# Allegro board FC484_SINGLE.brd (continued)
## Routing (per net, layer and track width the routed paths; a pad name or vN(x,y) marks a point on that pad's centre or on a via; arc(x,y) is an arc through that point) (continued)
IO51: length 6.3
  TOP w0.254: U1.K5 v1(47.81,61.23)
  L4_SIG2 w0.102: v1(47.81,61.23) 47.32,61.73 42.42,61.73
IO52: length 5.5
  TOP w0.254: U1.M4 v1(46.81,58.23)
  L3_SIG1 w0.102: v1(46.81,58.23) 46.32,58.73 44.45,58.73 43.95,58.23 42.45,58.23
IO53: length 4.2
  TOP w0.254: U1.L3 v1(45.81,60.23)
  L3_SIG1 w0.102: v1(45.81,60.23) 45.55,60.23 45.13,59.81 44.23,59.81 44.11,59.94 44.1,59.94 43.81,60.23 42.63,60.23
IO54: length 6.6
  TOP w0.254: U1.M5 v1(47.81,58.23)
  L3_SIG1 w0.102: v1(47.81,58.23) 46.96,59.09 43.96,59.09 43.81,59.23 43.81,59.23 43.63,59.41 42.43,59.41
IO55: length 6.5
  TOP w0.254: U1.L5 v1(47.81,60.23)
  L3_SIG1 w0.102: 42.56,59.87 43.67,59.87 43.95,59.59 43.96,59.59 44.09,59.46 47.04,59.46 v1(47.81,60.23)
IO56: length 2.4
  TOP w0.127: U1.L1 41.92,59.73
IO57: length 2.4
  TOP w0.127: U1.K1 41.92,60.73
IO58: length 3.9
  TOP w0.127: U1.J2 44.82,62.23 41.67,62.23
IO59: length 4
  TOP w0.254: U1.J3 v1(45.81,62.23)
  L3_SIG1 w0.102: v1(45.81,62.23) 44.32,62.23 44.25,62.17 42.58,62.17
IO60: length 3.9
  TOP w0.127: 41.67,60.23 44.82,60.23 U1.L2
IO61: length 4.3
  TOP w0.254: U1.K3 v1(45.81,61.23)
  L3_SIG1 w0.102: v1(45.81,61.23) 45.52,61.23 44.97,60.68 44.37,60.68 44.11,60.94 42.57,60.94
IO62: length 2.4
  TOP w0.127: U1.J1 41.92,61.73
IO63: length 2.4
  TOP w0.127: U1.H1 41.92,62.73
IO64: length 2.5
  TOP w0.127: U1.F1 41.77,64.73
IO65: length 3.9
  TOP w0.127: U1.F2 44.82,65.23 41.67,65.23
IO66: length 3.9
  TOP w0.127: U1.H2 44.82,63.23 41.67,63.23
IO67: length 3.9
  TOP w0.127: 41.67,64.23 44.82,64.23 U1.G2
IO68: length 7.3
  TOP w0.254: U1.F12 v1(55.81,65.23)
  L3_SIG1 w0.102: v1(55.81,65.23) 55.23,65.82 55.23,71.55
IO69: length 8
  TOP w0.254: U1.F13 v1(56.81,65.23)
  L4_SIG2 w0.102: v1(56.81,65.23) 56.81,65.26 56.34,65.73 55.61,65.73 55.26,66.09 55.26,71.49
IO70: length 7.4
  TOP w0.254: U1.F11 v1(53.81,65.23)
  L3_SIG1 w0.102: v1(53.81,65.23) 54.79,66.2 54.79,71.55
IO71: length 6.2
  TOP w0.254: U1.E11 v1(53.81,66.23)
  L3_SIG1 w0.102: 54.32,71.55 54.32,66.74 v1(53.81,66.23)
IO72: length 7.2
  TOP w0.254: U1.K6 v1(48.81,61.23)
  L4_SIG2 w0.102: 42.48,60.73 48.31,60.73 v1(48.81,61.23)
IO73: length 7.1
  TOP w0.254: U1.J6 v1(48.81,62.23)
  L4_SIG2 w0.102: v1(48.81,62.23) 48.32,62.73 42.63,62.73
IO74: length 9
  TOP w0.254: U1.J7 v1(49.81,62.23)
  L5_SIG3 w0.102: v1(49.81,62.23) 49.32,62.73 41.71,62.73
IO75: length 9.2
  TOP w0.254: U1.H7 v1(49.81,63.23)
  L5_SIG3 w0.102: 41.82,64.34 43.87,64.34 44.48,63.73 49.11,63.73 49.61,63.23 v1(49.81,63.23)
IO76: length 6.3
  TOP w0.254: U1.E13 v1(56.81,66.23)
  L4_SIG2 w0.102: 56.31,71.64 56.31,66.73 v1(56.81,66.23)
IO77: length 5.5
  TOP w0.254: U1.D13 v1(56.81,67.23)
  L3_SIG1 w0.102: 56.82,71.55 56.82,69.77 57.36,69.23 57.36,67.78 v1(56.81,67.23)
IO78: length 9.7
  TOP w0.254: U1.K8 v1(50.81,61.23)
  L5_SIG3 w0.102: v1(50.81,61.23) 50.32,61.73 42,61.73
IO79: length 11.5
  TOP w0.254: U1.J8 v1(50.81,62.23)
  L5_SIG3 w0.102: 41.84,65.1 43.72,65.1 44.09,64.73 49.02,64.73 49.31,64.44 49.31,64.03 49.61,63.73 50.02,63.73 50.31,63.44 50.31,62.73 v1(50.81,62.23)
IO80: length 4.9
  TOP w0.254: U1.J4 v1(46.81,62.23)
  L3_SIG1 w0.102: v1(46.81,62.23) 46.32,61.73 42.88,61.73
IO81: length 5.2
  TOP w0.254: U1.H4 v1(46.81,63.23)
  L3_SIG1 w0.102: v1(46.81,63.23) 46.32,62.73 44.32,62.73 44.11,62.52 42.63,62.52
IO82: length 6.7
  TOP w0.254: U1.H5 v1(47.81,63.23)
  L4_SIG2 w0.102: 42.28,64.24 43.93,64.24 44.45,63.73 47.32,63.73 v1(47.81,63.23)
IO83: length 8.3
  TOP w0.254: U1.H6 v1(48.81,63.23)
  L4_SIG2 w0.102: 42.28,64.73 48.02,64.73 48.31,64.44 48.31,63.73 v1(48.81,63.23)
IO84: length 11
  TOP w0.254: U1.K9 v1(51.81,61.23)
  L5_SIG3 w0.102: 42.67,59.37 50.65,59.37 51.31,60.03 51.31,60.73 v1(51.81,61.23)
IO85: length 10
  TOP w0.254: U1.J9 v1(51.81,62.23)
  L5_SIG3 w0.102: v1(51.81,62.23) 51.31,62.73 51.31,71.28
IO86: length 2.5
  TOP w0.127: U1.D1 41.77,66.73
IO87: length 2.5
  TOP w0.127: U1.E1 41.77,65.73
IO88: length 3.9
  TOP w0.127: 41.67,68.23 44.82,68.23 U1.C2
IO89: length 3.9
  TOP w0.127: U1.D2 44.82,67.23 41.67,67.23
IO90: length 2.5
  TOP w0.127: U1.B1 41.77,68.73
IO91: length 2.5
  TOP w0.127: U1.C1 41.77,67.73
IO92: length 2.5
  TOP w0.127: U1.A3 46.31,72.26
IO93: length 2.5
  TOP w0.127: U1.A2 45.31,72.28
IO94: length 4.3
  TOP w0.254: U1.D3 v1(45.81,67.23)
  L3_SIG1 w0.102: v1(45.81,67.23) 42.21,67.23
IO95: length 4.2
  TOP w0.254: U1.E3 v1(45.81,66.23)
  L3_SIG1 w0.102: 42.57,65.73 45.02,65.73 45.52,66.23 v1(45.81,66.23)
IO96: length 3.5
  TOP w0.127: U1.B3 45.82,69.23 45.82,72.04
IO97: length 3.8
  TOP w0.127: 44.82,72.29 44.82,69.23 U1.B2
IO98: length 6.6
  TOP w0.254: U1.E14 v1(57.81,66.23)
  L4_SIG2 w0.102: 57.81,71.75 57.81,70.23 57.32,69.74 57.32,66.73 v1(57.81,66.23)
IO99: length 5
  TOP w0.254: U1.D14 v1(57.81,67.23)
  L3_SIG1 w0.102: v1(57.81,67.23) 57.81,71.55
IO100: length 7.2
  TOP w0.254: U1.E5 v1(47.81,66.23)
  L3_SIG1 w0.102: 42.25,67.73 46.02,67.73 46.31,67.44 46.31,66.97 46.54,66.73 47.1,66.73 47.6,66.23 v1(47.81,66.23)
IO101: length 6.3
  TOP w0.254: U1.F5 v1(47.81,65.23)
  L3_SIG1 w0.102: 42.63,65.28 45.08,65.28 45.54,65.73 47.32,65.73 v1(47.81,65.23)
IO102: length 4.1
  TOP w0.254: U1.C4 v1(46.81,68.23)
  L3_SIG1 w0.102: v1(46.81,68.23) 46.81,68.48 46.42,68.87 46.42,71.41
IO103: length 5.1
  TOP w0.254: U1.D4 v1(46.81,67.23)
  L3_SIG1 w0.102: v1(46.81,67.23) 46.81,67.53 46.32,68.03 46.32,68.19 46.31,68.19 46.31,68.48 46.06,68.72 46.06,71.32
IO104: length 5.4
  TOP w0.254: U1.E4 v1(46.81,66.23)
  L3_SIG1 w0.102: 42.36,66.73 46.02,66.73 46.52,66.23 v1(46.81,66.23)
IO105: length 4
  TOP w0.254: U1.F3 v1(45.81,65.23)
  L3_SIG1 w0.102: 42.63,64.89 45.21,64.89 45.55,65.23 v1(45.81,65.23)
IO106: length 2.5
  TOP w0.127: U1.A5 48.31,72.19
IO107: length 3.7
  TOP w0.127: 46.82,72.21 46.82,69.23 U1.B4
IO108: length 5.5
  TOP w0.254: U1.D6 v1(48.81,67.23)
  L3_SIG1 w0.102: v1(48.81,67.23) 48.31,67.73 48.31,68.51 47.81,69.02 47.81,69.73 48.17,70.09 48.17,71.42
IO109: length 6.7
  TOP w0.254: U1.E6 v1(48.81,66.23)
  L3_SIG1 w0.102: v1(48.81,66.23) 48.32,66.73 47.61,66.73 47.32,67.03 47.32,68.49 46.78,69.03 46.78,70.96
IO110: length 3.6
  TOP w0.127: 47.82,72.16 47.82,69.23 U1.B5
IO111: length 4.2
  TOP w0.254: U1.C5 v1(47.81,68.23)
  L3_SIG1 w0.102: v1(47.81,68.23) 47.81,68.5 47.4,68.92 47.4,69.82 47.81,70.23 47.81,71.41
IO112: length 4.1
  TOP w0.254: U1.C15 v1(58.81,68.23)
  L3_SIG1 w0.102: v1(58.81,68.23) 58.52,68.52 58.52,71.55
IO113: length 4.8
  TOP w0.127: U1.C14 57.81,68.23 57.81,72.36
IO114: length 3.9
  TOP w0.127: U1.B17 60.82,69.24 60.82,72.45
IO115: length 2.7
  TOP w0.127: U1.A17 60.31,72.44
IO116: length 3.9
  TOP w0.127: 58.81,72.44 58.81,69.23 U1.B15
IO117: length 3.9
  TOP w0.127: 56.81,72.44 56.81,69.24 U1.B14
IO118: length 4.1
  TOP w0.254: U1.C17 v1(60.81,68.23)
  L3_SIG1 w0.102: v1(60.81,68.23) 60.81,71.64
IO119: length 4.2
  TOP w0.254: U1.C16 v1(59.81,68.23)
  L3_SIG1 w0.102: v1(59.81,68.23) 59.81,68.49 59.3,69 59.3,71.55
IO120: length 2.7
  TOP w0.127: U1.A16 59.31,72.44
IO121: length 2.7
  TOP w0.127: U1.A15 58.31,72.44
IO122: length 4.9
  TOP w0.254: U1.D8 v1(50.81,67.23)
  L3_SIG1 w0.102: 50.32,71.25 50.32,67.73 v1(50.81,67.23)
IO123: length 6.3
  TOP w0.254: U1.E8 v1(50.81,66.23)
  L4_SIG2 w0.102: 51.31,71.66 51.31,66.73 v1(50.81,66.23)
IO124: length 12.5
  TOP w0.254: U1.H13 v1(56.81,63.23)
  L4_SIG2 w0.102: 67.58,61.73 57.61,61.73 57.32,62.03 57.32,62.73 v1(56.81,63.23)
IO125: length 8.1
  TOP w0.254: U1.G14 v1(57.81,64.23)
  L4_SIG2 w0.102: 58.31,71.39 58.31,64.73 v1(57.81,64.23)
IO126: length 9.3
  TOP w0.254: U1.G15 v1(58.81,64.23)
  L4_SIG2 w0.102: v1(58.81,64.23) 59.32,64.73 67.16,64.73
IO127: length 9.5
  TOP w0.254: U1.H15 v1(58.81,63.23)
  L4_SIG2 w0.102: 67.41,62.73 59.31,62.73 v1(58.81,63.23)
IO128: length 5.2
  TOP w0.254: U1.D17 v1(60.81,67.23)
  L3_SIG1 w0.102: v1(60.81,67.23) 61.32,67.73 61.32,71.56
IO129: length 5.2
  TOP w0.254: U1.D16 v1(59.81,67.23)
  L3_SIG1 w0.102: v1(59.81,67.23) 60.31,67.73 60.31,71.51
IO130: length 6.4
  TOP w0.254: U1.E16 v1(59.81,66.23)
  L3_SIG1 w0.102: 58.88,71.55 58.88,68.92 59.32,68.48 59.32,66.73 v1(59.81,66.23)
IO131: length 6.3
  TOP w0.254: U1.E15 v1(58.81,66.23)
  L3_SIG1 w0.102: v1(58.81,66.23) 58.32,66.73 58.32,68.22 58.17,68.37 58.17,71.55
IO132: length 7.7
  TOP w0.254: U1.F17 v1(60.81,65.23)
  L4_SIG2 w0.102: v1(60.81,65.23) 61.31,65.73 61.31,72
IO133: length 7.4
  TOP w0.254: U1.G17 v1(60.81,64.23)
  L4_SIG2 w0.102: 67.29,63.73 61.32,63.73 v1(60.81,64.23)
IO134: length 7.6
  TOP w0.254: U1.F16 v1(59.81,65.23)
  L4_SIG2 w0.102: 60.31,71.94 60.31,65.73 v1(59.81,65.23)
IO135: length 7.4
  TOP w0.254: U1.F15 v1(58.81,65.23)
  L4_SIG2 w0.102: v1(58.81,65.23) 59.31,65.73 59.31,71.74
IO136: length 2.5
  TOP w0.127: U1.A7 50.31,72.19
IO137: length 2.5
  TOP w0.127: U1.A6 49.31,72.19
IO138: length 5.1
  TOP w0.254: U1.D9 v1(51.81,67.23)
  L3_SIG1 w0.102: v1(51.81,67.23) 51.31,67.73 51.31,68.48 51.06,68.72 51.06,71.32
IO139: length 6.8
  TOP w0.254: U1.E9 v1(51.81,66.23)
  L4_SIG2 w0.102: 51.76,71.93 51.76,70.29 52.31,69.74 52.31,66.73 v1(51.81,66.23)
IO140: length 2.5
  TOP w0.127: U1.A8 51.31,72.19
IO141: length 3.7
  TOP w0.127: U1.B8 50.82,69.23 50.82,72.22
IO142: length 3.9
  TOP w0.127: 55.82,72.38 55.82,69.23 U1.B13
IO143: length 4.1
  TOP w0.127: 54.82,72.59 54.82,69.23 U1.B12
IO144: length 4.2
  TOP w0.254: U1.C10 v1(52.81,68.23)
  L3_SIG1 w0.102: v1(52.81,68.23) 52.81,68.5 52.4,68.92 52.4,69.82 52.81,70.23 52.81,71.41
IO145: length 4.1
  TOP w0.254: U1.C9 v1(51.81,68.23)
  L3_SIG1 w0.102: 51.42,71.41 51.42,68.87 51.81,68.48 v1(51.81,68.23)
IO146: length 3.7
  TOP w0.127: 52.81,72.22 52.81,69.23 U1.B10
IO147: length 3.7
  TOP w0.127: U1.B9 51.82,69.23 51.82,72.27
IO148: length 4
  TOP w0.254: U1.C12 v1(55.81,68.23)
  L3_SIG1 w0.102: v1(55.81,68.23) 55.81,71.55
IO149: length 4.3
  TOP w0.254: U1.C11 v1(53.81,68.23)
  L3_SIG1 w0.102: v1(53.81,68.23) 53.81,68.53 53.26,69.08 53.26,69.68 53.52,69.94 53.52,71.48
IO150: length 7.3
  TOP w0.254: U1.T11 v1(53.81,54.23)
  L4_SIG2 w0.102: v1(53.81,54.23) 54.21,54.23 54.81,53.64 54.81,48.33
IO151: length 13.6
  TOP w0.254: U1.R12 v1(55.81,55.23)
  L4_SIG2 w0.102: 67.02,57.73 57.61,57.73 57.31,57.44 57.31,57.03 57.02,56.73 56.61,56.73 56.31,56.44 56.31,55.73 55.82,55.23 v1(55.81,55.23)
IO152: length 6
  TOP w0.254: U1.U14 v1(57.81,53.23)
  L4_SIG2 w0.102: v1(57.81,53.23) 58.31,52.73 58.31,48.14
IO153: length 6.1
  TOP w0.254: U1.V14 v1(57.81,52.23)
  L3_SIG1 w0.102: v1(57.81,52.23) 57.32,51.73 57.32,47.03
IO154: length 4.3
  TOP w0.254: U1.Y9 v1(51.81,50.23)
  L3_SIG1 w0.102: v1(51.81,50.23) 51.81,49.94 52.37,49.39 52.37,49.01 52.1,48.75 52.1,46.99
IO155: length 5.5
  TOP w0.254: U1.W9 v1(51.81,51.23)
  L3_SIG1 w0.102: 52.46,47.05 52.46,48.59 52.82,48.95 52.82,49.45 52.32,49.96 52.32,50.73 v1(51.81,51.23)
IO156: length 4.5
  TOP w0.254: U1.V10 v1(52.81,52.23)
  L4_SIG2 w0.102: 52.32,48.62 52.32,51.73 v1(52.81,52.23)
IO157: length 5.8
  TOP w0.254: U1.V9 v1(51.81,52.23)
  L3_SIG1 w0.102: v1(51.81,52.23) 51.32,51.73 51.32,47.32
IO158: length 8.4
  TOP w0.254: U1.R10 v1(52.81,55.23)
  L5_SIG3 w0.102: 53.31,47.79 53.31,54.73 v1(52.81,55.23)
IO159: length 8.4
  TOP w0.254: U1.R9 v1(51.81,55.23)
  L5_SIG3 w0.102: 52.31,47.78 52.31,54.73 v1(51.81,55.23)
IO160: length 7
  TOP w0.254: U1.U10 v1(52.81,53.23)
  L4_SIG2 w0.102: v1(52.81,53.23) 53.31,52.73 53.31,48.66 53.01,48.35 53.01,47.32
IO161: length 8.8
  TOP w0.254: U1.T10 v1(52.81,54.23)
  L4_SIG2 w0.102: v1(52.81,54.23) 53.31,53.73 54.02,53.73 54.37,53.39 54.37,48.78 53.67,48.08 53.67,47.47
IO162: length 5.7
  TOP w0.254: U1.U9 v1(51.81,53.23)
  L4_SIG2 w0.102: v1(51.81,53.23) 51.32,52.73 51.32,48.49
IO163: length 5.3
  TOP w0.254: U1.U8 v1(50.81,53.23)
  L4_SIG2 w0.102: v1(50.81,53.23) 50.81,53.03 50.32,52.53 50.32,48.8
IO164: length 7.9
  TOP w0.254: U1.T8 v1(50.81,54.23)
  L4_SIG2 w0.102: v1(50.81,54.23) 50.31,53.73 50.31,53.03 50.02,52.73 49.61,52.73 49.31,52.43 49.31,52.03 49.02,51.73 48.61,51.73 48.32,51.44 48.32,48.54
IO165: length 8.3
  TOP w0.254: U1.T7 v1(49.81,54.23)
  L4_SIG2 w0.102: v1(49.81,54.23) 49.31,53.73 44.32,53.73 43.81,53.22 42.62,53.22
IO166: length 3.8
  TOP w0.254: U1.Y8 v1(50.81,50.23)
  L3_SIG1 w0.102: v1(50.81,50.23) 50.81,47.15
IO167: length 3.9
  TOP w0.127: U1.AA8 50.82,49.23 50.82,46.09
IO168: length 2.7
  TOP w0.127: U1.AB7 50.31,45.99
IO169: length 3.9
  TOP w0.127: 49.82,46.09 49.82,49.23 U1.AA7
IO170: length 4.9
  TOP w0.254: U1.W8 v1(50.81,51.23)
  L3_SIG1 w0.102: 50.32,47.27 50.32,50.73 v1(50.81,51.23)
IO171: length 5
  TOP w0.254: U1.W7 v1(49.81,51.23)
  L3_SIG1 w0.102: v1(49.81,51.23) 49.32,50.73 49.32,48.73 49.82,48.22 49.82,47.38
IO172: length 2.9
  TOP w0.127: U1.AB5 48.31,45.86
IO173: length 3.9
  TOP w0.127: U1.AA5 47.82,49.23 47.82,46.09
IO174: length 3.9
  TOP w0.127: U1.AA6 48.82,49.23 48.82,46.09
IO175: length 3.6
  TOP w0.254: U1.Y6 v1(48.81,50.23)
  L3_SIG1 w0.102: v1(48.81,50.23) 48.81,47.33
IO176: length 4.3
  TOP w0.254: U1.V7 v1(49.81,52.23)
  L4_SIG2 w0.102: v1(49.81,52.23) 49.81,52.03 49.32,51.53 49.32,48.82
IO177: length 8.2
  TOP w0.254: U1.U7 v1(49.81,53.23)
  L4_SIG2 w0.102: v1(49.81,53.23) 49.6,53.23 49.1,52.73 42.58,52.73
IO178: length 2.9
  TOP w0.127: U1.AB4 47.31,45.86
IO179: length 2.9
  TOP w0.127: U1.AB3 46.31,45.86
IO180: length 4.9
  TOP w0.254: U1.W6 v1(48.81,51.23)
  L3_SIG1 w0.102: 48.32,47.27 48.32,50.73 v1(48.81,51.23)
IO181: length 6.5
  TOP w0.254: U1.V6 v1(48.81,52.23)
  L4_SIG2 w0.102: 43.2,51.73 48.1,51.73 48.61,52.23 v1(48.81,52.23)
IO182: length 2.9
  TOP w0.127: U1.AB2 45.31,45.86
IO183: length 3.9
  TOP w0.127: 44.82,46.09 44.82,49.23 U1.AA2
IO184: length 3.9
  TOP w0.254: U1.Y5 v1(47.81,50.23)
  L3_SIG1 w0.102: v1(47.81,50.23) 47.81,48.12 47.82,48.12 47.82,47.05
IO185: length 4.1
  TOP w0.254: U1.Y4 v1(46.81,50.23)
  L3_SIG1 w0.102: 46.24,47.04 46.24,49.36 46.81,49.94 v1(46.81,50.23)
IO186: length 3.9
  TOP w0.127: U1.AA3 45.82,49.23 45.82,46.09
IO187: length 4.1
  TOP w0.254: U1.Y3 v1(45.81,50.23)
  L3_SIG1 w0.102: v1(45.81,50.23) 45.32,49.73 42.67,49.73
IO188: length 5.4
  TOP w0.254: U1.W4 v1(46.81,51.23)
  L3_SIG1 w0.102: v1(46.81,51.23) 46.81,50.94 46.31,50.43 46.31,50.02 45.85,49.56 45.85,46.95
IO189: length 5.9
  TOP w0.254: U1.V5 v1(47.81,52.23)
  L3_SIG1 w0.102: v1(47.81,52.23) 47.81,52.03 47.32,51.53 47.32,47.21
IO190: length 2.2
  TOP w0.127: U1.AA1 42.07,49.73
IO191: length 2.2
  TOP w0.127: U1.Y1 42.07,50.73
IO192: length 3.8
  TOP w0.254: U1.W3 v1(45.81,51.23)
  L3_SIG1 w0.102: v1(45.81,51.23) 42.76,51.23
IO193: length 5.1
  TOP w0.254: U1.V4 v1(46.81,52.23)
  L3_SIG1 w0.102: 42.67,51.73 46.11,51.73 46.61,52.23 v1(46.81,52.23)
IO194: length 2.2
  TOP w0.127: U1.W1 42.07,51.73
IO195: length 2.2
  TOP w0.127: U1.V1 42.07,52.73
IO196: length 3.9
  TOP w0.127: U1.W2 44.82,51.23 41.67,51.23
IO197: length 3.9
  TOP w0.127: U1.V2 44.82,52.23 41.67,52.23
IO198: length 3.9
  TOP w0.127: U1.U2 44.82,53.23 41.67,53.23
IO199: length 4.1
  TOP w0.254: U1.U3 v1(45.81,53.23)
  L3_SIG1 w0.102: v1(45.81,53.23) 45.57,53.23 45.17,52.84 42.63,52.84
IO200: length 5.1
  TOP w0.254: U1.U4 v1(46.81,53.23)
  L3_SIG1 w0.102: v1(46.81,53.23) 46.31,52.73 45.57,52.73 45.32,52.48 42.73,52.48
IO201: length 7.4
  TOP w0.254: U1.U5 v1(47.81,53.23)
  L3_SIG1 w0.102: v1(47.81,53.23) 47.32,52.73 47.32,52.03 47.02,51.73 46.61,51.73 46.31,51.43 46.31,51.03 46.02,50.73 42.77,50.73
IO202: length 7.4
  TOP w0.254: U1.U17 v1(60.81,53.23)
  L4_SIG2 w0.102: v1(60.81,53.23) 61.32,52.73 67.25,52.73
IO203: length 10
  TOP w0.254: U1.T17 v1(60.81,54.23)
  L3_SIG1 w0.102: 65.84,59.2 64.18,59.2 63.74,58.77 61.65,58.77 61.31,58.43 61.31,54.73 v1(60.81,54.23)
IO204: length 5.3
  TOP w0.254: U1.W16 v1(59.81,51.23)
  L3_SIG1 w0.102: v1(59.81,51.23) 60.31,50.73 60.31,49.99 60.52,49.78 60.52,46.92
IO205: length 4.7
  TOP w0.254: U1.V16 v1(59.81,52.23)
  L4_SIG2 w0.102: v1(59.81,52.23) 59.82,52.23 60.32,51.73 60.32,48.47
IO206: length 7.5
  TOP w0.254: U1.V17 v1(60.81,52.23)
  L4_SIG2 w0.102: v1(60.81,52.23) 61.32,51.73 67.39,51.73
IO207: length 5.2
  TOP w0.254: U1.W17 v1(60.81,51.23)
  L3_SIG1 w0.102: 61.31,46.95 61.31,50.73 v1(60.81,51.23)
IO208: length 3.9
  TOP w0.127: 60.81,46.09 60.81,49.23 U1.AA17
IO209: length 2.9
  TOP w0.127: U1.AB17 60.31,45.88
IO210: length 4.2
  TOP w0.254: U1.Y16 v1(59.81,50.23)
  L3_SIG1 w0.102: v1(59.81,50.23) 59.81,49.99 60.17,49.63 60.17,46.87
IO211: length 3.9
  TOP w0.127: 59.81,46.09 59.81,49.23 U1.AA16
IO212: length 9.9
  TOP w0.254: U1.R16 v1(59.81,55.23)
  L3_SIG1 w0.102: v1(59.81,55.23) 60.32,55.73 60.32,58.51 60.95,59.14 63.61,59.14 64.1,59.63 65.6,59.63
IO213: length 8.3
  TOP w0.254: U1.T16 v1(59.81,54.23)
  L4_SIG2 w0.102: v1(59.81,54.23) 60.31,53.73 67.2,53.73
IO214: length 3.9
  TOP w0.127: U1.AA15 58.81,49.23 58.81,46.09
IO215: length 4.2
  TOP w0.254: U1.Y15 v1(58.81,50.23)
  L3_SIG1 w0.102: v1(58.81,50.23) 58.81,49.97 59.23,49.55 59.23,48.65 58.82,48.23 58.82,47.05
IO216: length 4.3
  TOP w0.254: U1.Y14 v1(57.81,50.23)
  L3_SIG1 w0.102: 58.1,46.99 58.1,48.53 58.37,48.79 58.37,49.4 57.81,49.96 v1(57.81,50.23)
IO217: length 5.5
  TOP w0.254: U1.W14 v1(57.81,51.23)
  L3_SIG1 w0.102: v1(57.81,51.23) 58.32,50.73 58.32,49.96 58.82,49.45 58.82,48.74 58.46,48.38 58.46,47.05
IO218: length 2.8
  TOP w0.127: U1.AB15 58.31,45.95
IO219: length 2.8
  TOP w0.127: U1.AB14 57.31,45.95
IO220: length 2.8
  TOP w0.127: U1.AB12 55.31,45.95
IO221: length 3.9
  TOP w0.127: U1.AA12 54.82,49.23 54.82,46.09
IO222: length 2.8
  TOP w0.127: U1.AB13 56.31,45.95
IO223: length 3.9
  TOP w0.127: U1.AA13 55.82,49.23 55.82,46.09
IO224: length 5
  TOP w0.127: U1.Y13 56.81,50.23 56.81,45.97
IO225: length 4.9
  TOP w0.254: U1.W13 v1(56.81,51.23)
  L3_SIG1 w0.102: 56.81,47.07 v1(56.81,51.23)
IO226: length 2.7
  TOP w0.127: U1.AB10 53.31,45.99
IO227: length 3.9
  TOP w0.127: 52.82,46.09 52.82,49.23 U1.AA10
IO228: length 3.9
  TOP w0.127: 53.82,46.09 53.82,49.23 U1.AA11
IO229: length 4.1
  TOP w0.254: U1.Y11 v1(53.81,50.23)
  L3_SIG1 w0.102: 53.7,46.97 53.7,48.19 53.95,48.44 53.95,50.1 v1(53.81,50.23)
IO230: length 5.2
  TOP w0.254: U1.W12 v1(55.81,51.23)
  L3_SIG1 w0.102: v1(55.81,51.23) 55.32,50.73 55.32,49 55.71,48.61 55.71,47.08
IO231: length 6.4
  TOP w0.254: U1.V12 v1(55.81,52.23)
  L3_SIG1 w0.102: v1(55.81,52.23) 54.96,51.38 54.96,48.86 55.36,48.46 55.36,47.08
IO232: length 2.7
  TOP w0.127: U1.AB9 52.31,45.99
IO233: length 2.7
  TOP w0.127: U1.AB8 51.31,45.99
IO234: length 4.2
  TOP w0.254: U1.Y10 v1(52.81,50.23)
  L3_SIG1 w0.102: 52.82,47.05 52.82,48.44 53.23,48.85 53.23,49.55 52.81,49.97 v1(52.81,50.23)
IO235: length 5.5
  TOP w0.254: U1.W11 v1(53.81,51.23)
  L3_SIG1 w0.102: v1(53.81,51.23) 53.32,50.73 53.32,49.97 53.59,49.69 53.59,48.69 53.17,48.27 53.17,46.97
IO236: length 6.4
  TOP w0.254: U1.V11 v1(53.81,52.23)
  L3_SIG1 w0.102: v1(53.81,52.23) 54.6,51.44 54.6,48.44 54.96,48.08 54.96,47.01
IO237: length 6.1
  TOP w0.254: U1.U12 v1(55.81,53.23)
  L4_SIG2 w0.102: v1(55.81,53.23) 55.32,52.73 55.32,48.02
IO238: length 9.2
  TOP w0.254: U1.R15 v1(58.81,55.23)
  L4_SIG2 w0.102: 67.07,55.73 59.31,55.73 v1(58.81,55.23)
IO239: length 9.2
  TOP w0.254: U1.T15 v1(58.81,54.23)
  L4_SIG2 w0.102: 67.07,54.73 59.31,54.73 v1(58.81,54.23)
IO240: length 7.1
  TOP w0.254: U1.U13 v1(56.81,53.23)
  L3_SIG1 w0.102: 56.32,47.04 56.32,52.73 v1(56.81,53.23)
IO241: length 6.8
  TOP w0.254: U1.T13 v1(56.81,54.23)
  L4_SIG2 w0.102: 57.32,48.32 57.32,53.73 v1(56.81,54.23)
IO242: length 5.5
  TOP w0.254: U1.U15 v1(58.81,53.23)
  L4_SIG2 w0.102: 58.81,53.22 v1(58.81,53.23) 59.32,52.73 59.32,48.7
IO243: length 6.3
  TOP w0.254: U1.V15 v1(58.81,52.23)
  L3_SIG1 w0.102: 59.81,47.05 59.81,49.47 59.31,49.97 59.31,51.73 v1(58.81,52.23)
IO244: length 6.7
  TOP w0.254: U1.T12 v1(55.81,54.23)
  L4_SIG2 w0.102: 56.31,48.4 56.31,53.73 v1(55.81,54.23)
IO245: length 11.8
  TOP w0.254: U1.R13 v1(56.81,55.23)
  L4_SIG2 w0.102: v1(56.81,55.23) 57.32,55.73 58.02,55.73 58.32,56.03 58.32,56.44 58.61,56.73 67.01,56.73
IO246: length 7.4
  TOP w0.254: U1.F8 v1(50.81,65.23)
  L4_SIG2 w0.102: v1(50.81,65.23) 50.32,65.73 50.32,71.73
IO247: length 7.6
  TOP w0.254: U1.G8 v1(50.81,64.23)
  L5_SIG3 w0.102: v1(50.81,64.23) 50.32,64.73 50.32,70.96
IO248: length 7.5
  TOP w0.254: U1.F6 v1(48.81,65.23)
  L4_SIG2 w0.102: v1(48.81,65.23) 48.61,65.23 48.11,65.73 42.24,65.73
IO249: length 7.1
  TOP w0.254: U1.F7 v1(49.81,65.23)
  L4_SIG2 w0.102: v1(49.81,65.23) 49.81,65.44 49.32,65.94 49.32,71.39
IO250: length 9.1
  TOP w0.254: U1.G7 v1(49.81,64.23)
  L4_SIG2 w0.102: v1(49.81,64.23) 49.31,64.73 49.31,65.44 49.02,65.73 48.61,65.73 48.31,66.03 48.31,66.44 48.02,66.73 43.12,66.73
IO251: length 9.8
  TOP w0.254: U1.H11 v1(53.81,63.23)
  L5_SIG3 w0.102: 55.18,71.35 55.18,63.99 54.43,63.23 v1(53.81,63.23)
IO252: length 8.4
  TOP w0.254: U1.G9 v1(51.81,64.23)
  L5_SIG3 w0.102: v1(51.81,64.23) 52.31,64.73 52.31,69.18 51.82,69.68 51.82,71.48
IO253: length 10
  TOP w0.254: U1.H10 v1(52.81,63.23)
  L5_SIG3 w0.102: v1(52.81,63.23) 53.07,63.23 53.57,63.73 54.21,63.73 54.67,64.19 54.67,71.19
IO254: length 4.2
  TOP w0.254: U1.G3 v1(45.81,64.23)
  L3_SIG1 w0.102: 42.7,63.23 43.81,63.23 44.67,64.09 45.42,64.09 45.57,64.23 v1(45.81,64.23)
IO255: length 8.3
  TOP w0.254: U1.G10 v1(52.81,64.23)
  L5_SIG3 w0.102: 53.31,71.64 53.31,65.02 52.81,64.52 v1(52.81,64.23)
IO256: length 6.2
  TOP w0.254: U1.G5 v1(47.81,64.23)
  L3_SIG1 w0.102: 42.59,64.51 45.33,64.51 45.55,64.73 47.32,64.73 v1(47.81,64.23)
IO257: length 5.3
  TOP w0.254: U1.G4 v1(46.81,64.23)
  L3_SIG1 w0.102: 42.78,62.88 43.96,62.88 44.81,63.73 46.31,63.73 v1(46.81,64.23)
SERDES_0_INT_REFCLK_N: length 4.6
  TOP w0.254: U1.R20 v1(63.81,55.23)
  BOTTOM w0.127: v1(63.81,55.23) 63.98,55.07 64.2,55.07 64.82,54.46 67.4,54.46
SERDES_0_INT_REFCLK_P: length 5.8
  TOP w0.254: U1.R19 v1(62.81,55.23)
  BOTTOM w0.127: v1(62.81,55.23) 63.31,54.74 64.07,54.74 64.68,54.13 67.4,54.13
SERDES_0_RX0_N: length 5.1
  TOP w0.127: 69.17,58.23 64.81,58.23 U1.M21
SERDES_0_RX0_P: length 3.9
  TOP w0.127: 69.17,58.56 65.48,58.56 U1.M22
SERDES_0_RX1_N: length 5.1
  TOP w0.127: 69.17,54.23 64.81,54.23 U1.T21
SERDES_0_RX1_P: length 3.9
  TOP w0.127: 69.17,54.56 65.48,54.56 U1.T22
SERDES_0_RX2_N: length 5.8
  TOP w0.254: U1.W19 v1(62.81,51.23)
  BOTTOM w0.127: v1(62.81,51.23) 63.31,50.74 64.07,50.74 64.68,50.13 67.4,50.13
SERDES_0_RX2_P: length 4.6
  TOP w0.254: U1.W20 v1(63.81,51.23)
  BOTTOM w0.127: v1(63.81,51.23) 63.98,51.07 64.2,51.07 64.82,50.46 67.4,50.46
SERDES_0_RX3_N: length 5.8
  TOP w0.254: U1.AA19 v1(62.81,49.23)
  BOTTOM w0.127: 67.4,48.13 64.68,48.13 64.07,48.74 63.31,48.74 v1(62.81,49.23)
SERDES_0_RX3_P: length 4.6
  TOP w0.254: U1.AA20 v1(63.81,49.23)
  BOTTOM w0.127: 67.4,48.46 64.82,48.46 64.2,49.07 63.98,49.07 v1(63.81,49.23)
SERDES_0_TX0_N: length 5.1
  TOP w0.127: U1.P21 64.81,56.23 69.17,56.23
SERDES_0_TX0_P: length 3.9
  TOP w0.127: U1.P22 65.48,56.56 69.17,56.56
SERDES_0_TX1_N: length 5.1
  TOP w0.127: U1.V21 64.81,52.23 69.17,52.23
SERDES_0_TX1_P: length 3.9
  TOP w0.127: 69.17,52.56 65.48,52.56 U1.V22
SERDES_0_TX2_N: length 5.1
  TOP w0.127: U1.Y21 64.81,50.23 69.17,50.23
SERDES_0_TX2_P: length 3.9
  TOP w0.127: U1.Y22 65.48,50.56 69.17,50.56
SERDES_0_TX3_N: length 6.2
  TOP w0.127: U1.AB21 64.65,48.4 64.65,47.73 65.21,47.17 69.44,47.17
SERDES_0_TX3_P: length 5.6
  TOP w0.127: 69.44,47.5 65.35,47.5 64.98,47.87 64.98,48.4 U1.AB22
SERDES_0N_EXT_REFCLK_N: length 4.6
  TOP w0.254: U1.U20 v1(63.81,53.23)
  BOTTOM w0.127: v1(63.81,53.23) 63.98,53.07 64.2,53.07 64.82,52.46 67.4,52.46
SERDES_0N_EXT_REFCLK_P: length 5.8
  TOP w0.254: U1.U19 v1(62.81,53.23)
  BOTTOM w0.127: v1(62.81,53.23) 63.31,52.74 64.07,52.74 64.68,52.13 67.4,52.13
SERDES_0S_EXT_REFCLK_N: length 4.6
  TOP w0.254: U1.N20 v1(63.81,57.23)
  BOTTOM w0.127: 67.4,56.46 64.82,56.46 64.2,57.07 63.98,57.07 v1(63.81,57.23)
SERDES_0S_EXT_REFCLK_P: length 5.8
  TOP w0.254: U1.N19 v1(62.81,57.23)
  BOTTOM w0.127: v1(62.81,57.23) 63.31,56.74 64.07,56.74 64.68,56.13 67.4,56.13
SERDES_01_EXT_REFCLK_N: length 4.6
  TOP w0.254: U1.J20 v1(63.81,62.23)
  BOTTOM w0.127: 67.4,61.46 64.82,61.46 64.2,62.07 63.98,62.07 v1(63.81,62.23)
SERDES_01_EXT_REFCLK_P: length 5.8
  TOP w0.254: U1.J19 v1(62.81,62.23)
  BOTTOM w0.127: v1(62.81,62.23) 63.31,61.74 64.07,61.74 64.68,61.13 67.4,61.13
SERDES_1_INT_REFCLK_N: length 4.6
  TOP w0.254: U1.G20 v1(63.81,64.23)
  BOTTOM w0.127: v1(63.81,64.23) 63.98,64.07 64.2,64.07 64.82,63.46 67.4,63.46
SERDES_1_INT_REFCLK_P: length 5.8
  TOP w0.254: U1.G19 v1(62.81,64.23)
  BOTTOM w0.127: 67.4,63.13 64.68,63.13 64.07,63.74 63.31,63.74 v1(62.81,64.23)
SERDES_1_RX0_N: length 7.9
  TOP w0.127: 68.99,71.63 63.52,71.63 62.65,70.76 62.65,70.07 U1.A19
SERDES_1_RX0_P: length 7.3
  TOP w0.127: U1.A20 62.98,70.07 62.98,70.62 63.66,71.3 68.99,71.3
SERDES_1_RX1_N: length 5.8
  TOP w0.254: U1.C19 v1(62.81,68.23)
  BOTTOM w0.127: v1(62.81,68.23) 63.31,67.74 64.07,67.74 64.68,67.13 67.4,67.13
SERDES_1_RX1_P: length 4.6
  TOP w0.254: U1.C20 v1(63.81,68.23)
  BOTTOM w0.127: v1(63.81,68.23) 63.98,68.07 64.2,68.07 64.82,67.46 67.4,67.46
SERDES_1_RX2_N: length 5.1
  TOP w0.127: U1.F21 64.81,65.23 69.17,65.23
SERDES_1_RX2_P: length 3.9
  TOP w0.127: U1.F22 65.48,64.9 69.17,64.9
SERDES_1_RX3_N: length 5.8
  TOP w0.254: U1.L19 v1(62.81,60.23)
  BOTTOM w0.127: v1(62.81,60.23) 63.31,59.74 64.07,59.74 64.68,59.13 67.4,59.13
SERDES_1_RX3_P: length 4.6
  TOP w0.254: U1.L20 v1(63.81,60.23)
  BOTTOM w0.127: 67.4,59.46 64.82,59.46 64.2,60.07 63.98,60.07 v1(63.81,60.23)
SERDES_1_TX0_N: length 5.1
  TOP w0.127: U1.B21 64.81,69.23 69.17,69.23
SERDES_1_TX0_P: length 3.9
  TOP w0.127: 69.17,68.9 65.48,68.9 U1.B22
SERDES_1_TX1_N: length 5.1
  TOP w0.127: U1.D21 64.81,67.23 69.17,67.23
SERDES_1_TX1_P: length 3.9
  TOP w0.127: U1.D22 65.48,66.9 69.17,66.9
SERDES_1_TX2_N: length 5.1
  TOP w0.127: U1.H21 64.81,63.23 69.17,63.23
SERDES_1_TX2_P: length 3.9
  TOP w0.127: U1.H22 65.48,62.9 69.17,62.9
SERDES_1_TX3_N: length 5.1
  TOP w0.127: 69.17,61.23 64.81,61.23 U1.K21
SERDES_1_TX3_P: length 3.9
  TOP w0.127: U1.K22 65.48,60.9 69.17,60.9
SERDES_13_EXT_REFCLK_N: length 4.6
  TOP w0.254: U1.E20 v1(63.81,66.23)
  BOTTOM w0.127: 67.4,65.46 64.82,65.46 64.2,66.07 63.98,66.07 v1(63.81,66.23)
SERDES_13_EXT_REFCLK_P: length 5.8
  TOP w0.254: U1.E19 v1(62.81,66.23)
  BOTTOM w0.127: 67.4,65.13 64.68,65.13 64.07,65.74 63.31,65.74 v1(62.81,66.23)
SERDES_VREF: length 1.4
  TOP w0.254: U1.F19 v1(62.81,65.23) ; U1.D19 v1(62.81,67.23)

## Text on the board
BOTTOM: Layer 14 (BOTTOM)
Ref Des/Assembly Bottom: ASSEMBLY_BOTTOM
Ref Des/Silkscreen Bottom: 305-PD-1X-XXXX | MICROSEMI TECHNICAL SUPPORT | +1(800) 262-1060
TOP: Layer 1 (TOP)
Ref Des/Assembly Top: ASSEMBLY_TOP
Ref Des/Silkscreen Top: RT4G_DEVELOPMENT_KIT REV A | DVP-101-000XXX-001
FAB_DATA: 4.0 MILS | 6.5 MILS | 50 OHM | SINGLE | 3.5/8.0 MILS | DIFFERENTIAL | 5 / 8 MILS | 100 OHM | 5.1 / 4.9 MILS | 90 OHM | REV | 1 | INTIAL RELEASE | DESCRIPTION | REVISIONS | XXXXXXXX | DATE | APPROVAL | 10.  VIAS IN THIS REGION NEEDS VIA PLUGGING FROM BOTTOM SIDE. | 14.  IMPEDANCE TOLERANCE SHOULD BE +/- 5% ON L1, L12, L14. REST OF THE LAYRES CAN HAVE 10% TOLERANCE | 11.  BOARD MUST BE UL 94V-1 APPROVED. | 12.  FABRICATE BOARD PER IPC-A-600D STANDARD. | 13.  CLIP SILKSCREEN ON NO MASK AREA. | 17.  REMOVE UNUSED PADS IN ALL INNER LAYERS. | 18.  BOARD DIMENSIONS ARE IN INCHES | 15.  NO VENDOR LOGO, ART WORKS SHOULD NOT BE | 20.  THIS IS A ROHS COMPLIANT BOARD | 19.  WARP & TWIST: SHALL NOT EXCEED 0.005 INCHES PER INCH | 2.1. SELECTIVE HARD GOLD PLATING TO BE FLAT & | 16.  DEBURR ALL SHARP EDGES | 21.  EDGE FINGER- CHAMFER EDGES MUST BE FREE OF CUTTING BURRS | 5.  SILKSCREEN BOTH SIDES, WHITE. | 7.  SOLDER MASK TOP AND BOTTOM SIDES WITH | 6.  FABRICATE PER DIMENSIONS SHOWN. | PLATING IN HOLES TO BE 0.001 MIN. THICK. | 4.  HOLE SIZES ARE AFTER PLATING. | 3.  HOLES TO BE PLATED THROUGH. | 9.  APPLY THIEVING AS REQUIRED. | 8.  TOTAL BOARD THICKNESS:  62 mil+/- 6 mil | SOLDER MASK.  COLOR GREEN. | LIQUID PHOTO IMAGABLE OR DRY FILM | 14 LAYER CONSTRUCTION. | 2.  GENERAL PLATING - FLASH GOLD | NOTES: UNLESS OTHERWISE SPECIFIED | 1.  MATERIAL: FR-4. | ABOVE THE SOLDER RESIST SURFACE ON TOP AND BOTTOM | THE VIAS SHOULD BE SMOOTHENED TO BOARD SURFACE ON TOP AND BOTTOM | GOLD PLATING ON PAD SHOULD BE THE SAME LEVEL OR | FOR SELECTIVE PLATING SEE BELOW | CHANGED WITHOUT PRIOR APPROVAL FROM PACTRON | PLATED 30uIN(MINIMUM) OF Au OVER 150-200uIN OF Ni. | NOTE: DIELECTRIC GLASS STYLE SHOULD NOT BE CHANGED WITHOUT PRIOR APPROVAL FROM PACTRON. | GLASS STYLE | DIELECTRIC | SHOULD NOT BE CHANGED FROM ABOVE STATED VALUES. | FINISHED TRACE WIDTH,AIR GAP OF 100 OHM DIFFERENTIAL AND 50 OHM SIGNLE ENDED | 2116 | STACKUP - 14 LAYERS | REFER STACKUP | CONTROLLED IMPEDANCE REQUIRED
User.17: FIGURE | SIZE | 125.0 | DRILL CHART: TOP to BOTTOM | ALL UNITS ARE IN MILS | TOLERANCE | +2.0/-2.0 | PLATED | NON-PLATED | QTY | 2
User.19: DATE: | FILM LAYER: | NAME: | XXXXXXXX | XXXXXXXXXXXXXXXXXXXX | REV: | A | PACTRON
User.20: FAB | PROJECT NAME | PART NUMBER | PACTRON | DATE | 3000 PATRICK HENRY DRIVE, SANTA CLARA, CA 95054. | 408-329-5500(PHONE), 408-747-1239(FAX). | XXXXXXXXXXXXXXXXXXXXXX | DVP-101-000XXX-001 | XXXXXXXX | 305-PD-15-XXXX | REV : | A
User.23: DIELECTRIC (4.00 mils) | DIELECTRIC (4.50 mils) | DIELECTRIC (3.50 mils) | DIELECTRIC (2.00 mils) | TOP (1.40 mils) | L2_GND1 (0.60 mils) | L3_SIG1 (0.60 mils) | L4_GND2 (0.60 mils) | L5_SIG2 (0.60 mils) | L6_GND3 (0.60 mils) | L7_PWR1 (1.30 mils) | L8_PWR2 (1.30 mils) | L9_GND4 (0.60 mils) | L10_SIG3 (0.60 mils) | L11_GND5 (0.60 mils) | L12_SIG4 (0.60 mils) | L13_GND6 (0.60 mils) | BOTTOM (1.40 mils) | FR-4
